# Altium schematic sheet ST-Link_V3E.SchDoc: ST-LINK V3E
size A3; Project: STLink V3 Embedded Prototype; BOM Version: A-01; Date: Not used; ApprovedBy: Not used; CheckedBy: Not used; Author: Not used; CompanyName: STMicroelectronics; DrawnBy: Not used; Engineer: Not used; Organization: Not used; Address1: Not used; Address2: Not used; Address3: Not used; Address4: Not used; DocumentNumber: 17; Revision: Not used; SheetNumber: 17; SheetTotal: 17
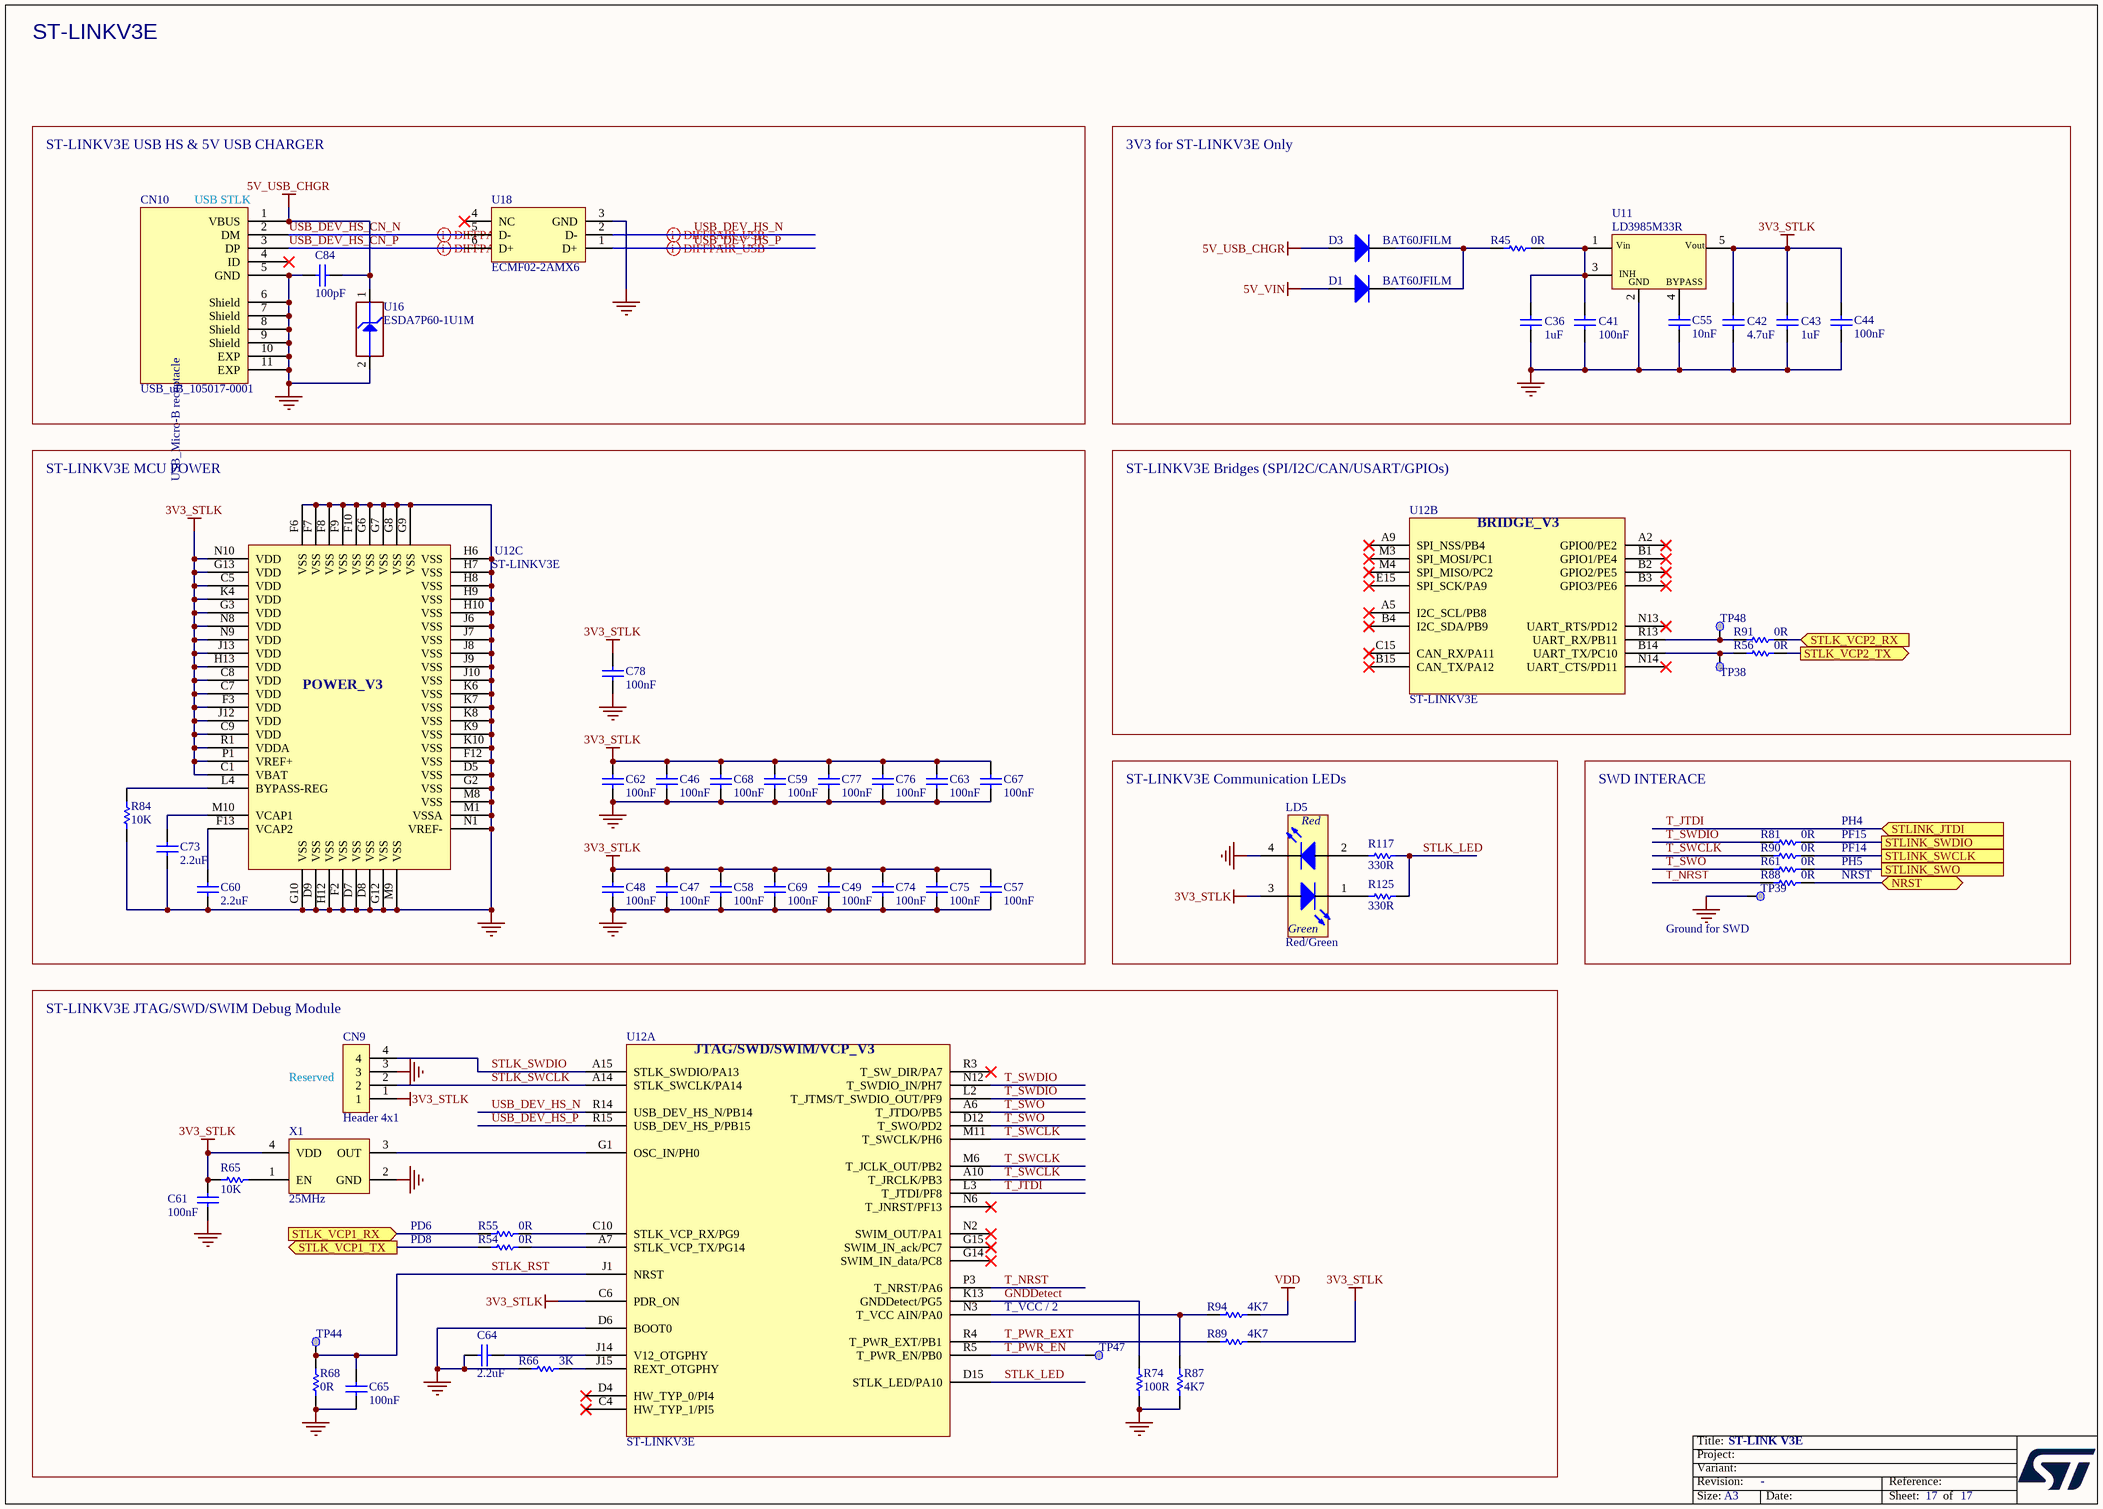
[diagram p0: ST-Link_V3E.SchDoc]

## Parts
C36  value 1uF  [C0402]  (hidden comment: Capacitor)
C41  value 100nF  [C0402]  (hidden comment: Capacitor)
C42  value 4.7uF  [C0402]  (hidden comment: Capacitor)
C43  value 1uF  [C0402]  (hidden comment: Capacitor)
C44  value 100nF  [C0402]  (hidden comment: Capacitor)
C46  value 100nF  [C0402]  (hidden comment: Capacitor)
C47  value 100nF  [C0402]  (hidden comment: Capacitor)
C48  value 100nF  [C0402]  (hidden comment: Capacitor)
C49  value 100nF  [C0402]  (hidden comment: Capacitor)
C55  value 10nF  [C0402]  (hidden comment: Capacitor)
C57  value 100nF  [C0402]  (hidden comment: Capacitor)
C58  value 100nF  [C0402]  (hidden comment: Capacitor)
C59  value 100nF  [C0402]  (hidden comment: Capacitor)
C60  value 2.2uF  [C0201_H0P5]  (hidden comment: Capacitor)
C61  value 100nF  [C0402]  (hidden comment: Capacitor)
C62  value 100nF  [C0402]  (hidden comment: Capacitor)
C63  value 100nF  [C0402]  (hidden comment: Capacitor)
C64  value 2.2uF  [C0201_H0P5]  (hidden comment: Capacitor)
C65  value 100nF  [C0402]  (hidden comment: Capacitor)
C67  value 100nF  [C0402]  (hidden comment: Capacitor)
C68  value 100nF  [C0402]  (hidden comment: Capacitor)
C69  value 100nF  [C0402]  (hidden comment: Capacitor)
C73  value 2.2uF  [C0201_H0P5]  (hidden comment: Capacitor)
C74  value 100nF  [C0402]  (hidden comment: Capacitor)
C75  value 100nF  [C0402]  (hidden comment: Capacitor)
C76  value 100nF  [C0402]  (hidden comment: Capacitor)
C77  value 100nF  [C0402]  (hidden comment: Capacitor)
C78  value 100nF  [C0402]  (hidden comment: Capacitor)
C84  value 100pF  [C0402]  (hidden comment: Capacitor)
CN9  Header 4x1  [CON_SAMTEC_TSW-104-07-G-S]
CN10  value USB_uB_105017-0001  [CON_USBMICROB_MOLEX_105017-0001_H2P90]  (hidden comment: USB_uB_105017.0001)
D1  BAT60JFILM  [DIO_SOD323]
D3  BAT60JFILM  [DIO_SOD323]
LD5  value Red/Green  [LED_BI-GR_CMD67-22]  (hidden comment: LD_BICOLOR_VCC)
R45  value 0R  [R0402]  (hidden comment: Resistor)
R54  value 0R  [R0402]  (hidden comment: Resistor)
R55  value 0R  [R0402]  (hidden comment: Resistor)
R56  value 0R  [R0402]  (hidden comment: Resistor)
R61  value 0R  [R0402]  (hidden comment: Resistor)
R65  value 10K  [R0402]  (hidden comment: Resistor)
R66  value 3K  [R0402]  (hidden comment: Resistor)
R68  value 0R  [R0402]  (hidden comment: Resistor)
R74  value 100R  [R0402]  (hidden comment: Resistor)
R81  value 0R  [R0402]  (hidden comment: Resistor)
R84  value 10K  [R0402]  (hidden comment: Resistor)
R87  value 4K7  [R0402]  (hidden comment: Resistor)
R88  value 0R  [R0402]  (hidden comment: Resistor)
R89  value 4K7  [R0402]  (hidden comment: Resistor)
R90  value 0R  [R0402]  (hidden comment: Resistor)
R91  value 0R  [R0402]  (hidden comment: Resistor)
R94  value 4K7  [R0402]  (hidden comment: Resistor)
R117  value 330R  [R0402]  (hidden comment: Resistor)
R125  value 330R  [R0402]  (hidden comment: Resistor)
TP38  Test Point  [TP_SMD_1MM]  (value not drawn)  (no BOM)
TP39  Test Point  [TP_SMD_1MM]  (value not drawn)  (no BOM)
TP44  Test Point  [TP_SMD_1MM]  (value not drawn)  (no BOM)
TP47  Test Point  [TP_SMD_1MM]  (value not drawn)  (no BOM)
TP48  Test Point  [TP_SMD_1MM]  (value not drawn)  (no BOM)
U11  LD3985M33R  [REG_SOT23-5L]
U12  ST-LINKV3E  [ICC_UFBGA201_176+25_10X10_P065]  (parts A,B,C of 3)
U16  value ESDA7P60-1U1M  [ESD_QFN2_1P6X1_P125]  (hidden comment: ESD-TRANSIL)
U18  ECMF02-2AMX6  [ESD_QFN-6L_1P7X1P5_P050]
X1  value 25MHz  [OSC_NDK_NZ2520SB_4P]  (hidden comment: OSCILLATOR_4_PINS)

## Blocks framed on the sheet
ST-LINKV3E USB HS & 5V USB CHARGER: C84 CN10 U16 U18
3V3 for ST-LINKV3E Only: C36 C41-C44 C55 D1 D3 R45 U11
ST-LINKV3E MCU POWER: C46-C49 C57-C60 C62 C63 C67-C69 C73-C78 R84 U12
ST-LINKV3E Bridges (SPI/I2C/CAN/USART/GPIOs): R56 R91 TP38 TP48 U12
ST-LINKV3E Communication LEDs: LD5 R117 R125
SWD INTERACE: R61 R81 R88 R90 TP39
ST-LINKV3E JTAG/SWD/SWIM Debug Module: C61 C64 C65 CN9 R54 R55 R65 R66 R68 R74 R87 R89 R94 TP44 TP47 U12 X1

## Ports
NRST (bidir), STLINK_JTDI (in), STLINK_SWCLK, STLINK_SWDIO, STLINK_SWO, STLK_VCP1_RX (in), STLK_VCP1_TX (out), STLK_VCP2_RX (in), STLK_VCP2_TX (out)

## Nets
3V3_STLK: C42.2 C43.2 C44.2 C46.2 C47.2 C48.2 C49.2 C57.2 C58.2 C59.2 C61.2 C62.2 C63.2 C67.2 C68.2 C69.2 C74.2 C75.2 C76.2 C77.2 C78.2 CN9.1 LD5.3(YellowGreen_anode) R65.1 R89.1 U11.5(Vout) U12.C1(VBAT) U12.C5(VDD) U12.C6(PDR_ON) U12.C7(VDD) U12.C8(VDD) U12.C9(VDD) U12.F3(VDD) U12.G3(VDD) U12.G13(VDD) U12.H13(VDD) U12.J12(VDD) U12.J13(VDD) U12.K4(VDD) U12.N8(VDD) U12.N9(VDD) U12.N10(VDD) U12.P1(VREF+) U12.R1(VDDA) X1.4(VDD)
5V_USB_CHGR: C84.2 CN10.1(VBUS) D3.1(A) U16.1(IO1)
5V_VIN: D1.1(A)
GND: C36.2 C41.1 C42.1 C43.1 C44.1 C46.1 C47.1 C48.1 C49.1 C55.1 C57.1 C58.1 C59.1 C60.1 C61.1 C62.1 C63.1 C64.1 C65.1 C67.1 C68.1 C69.1 C73.1 C74.1 C75.1 C76.1 C77.1 C78.1 C84.1 CN9.3 CN10.5(GND) CN10.6(Shield) CN10.7(Shield) CN10.8(Shield) CN10.9(Shield) CN10.10(EXP) CN10.11(EXP) LD5.4(RED_cathode) R66.1 R68.2 R74.1 R84.1 R87.1 TP39.1 U11.2(GND) U12.D5(VSS) U12.D6(BOOT0) U12.D7(VSS) U12.D8(VSS) U12.D9(VSS) U12.F2(VSS) U12.F6(VSS) U12.F7(VSS) U12.F8(VSS) U12.F9(VSS) U12.F10(VSS) U12.F12(VSS) U12.G2(VSS) U12.G6(VSS) U12.G7(VSS) U12.G8(VSS) U12.G9(VSS) U12.G10(VSS) U12.G12(VSS) U12.H6(VSS) U12.H7(VSS) U12.H8(VSS) U12.H9(VSS) U12.H10(VSS) U12.H12(VSS) U12.J6(VSS) U12.J7(VSS) U12.J8(VSS) U12.J9(VSS) U12.J10(VSS) U12.K6(VSS) U12.K7(VSS) U12.K8(VSS) U12.K9(VSS) U12.K10(VSS) U12.M1(VSSA) U12.M8(VSS) U12.M9(VSS) U12.N1(VREF-) U16.2(GND) U18.3(GND) X1.2(GND)
VDD: R94.2
GNDDetect: R74.2 U12.K13(GNDDetect/PG5)
NRST: R88.2 ; port NRST
STLINK_SWCLK: R90.2 ; port STLINK_SWCLK
STLINK_SWDIO: R81.2 ; port STLINK_SWDIO
STLINK_SWO: R61.2 ; port STLINK_SWO
STLK_LED: R117.2 R125.2 U12.D15(STLK_LED/PA10)
STLK_RST: C65.2 R68.1 TP44.1 U12.J1(NRST)
STLK_SWCLK: CN9.2 U12.A14(STLK_SWCLK/PA14)
STLK_SWDIO: CN9.4 U12.A15(STLK_SWDIO/PA13)
STLK_VCP1_RX: R55.2 ; port STLK_VCP1_RX
STLK_VCP1_TX: R54.2 ; port STLK_VCP1_TX
STLK_VCP2_RX: R91.1 ; port STLK_VCP2_RX
STLK_VCP2_TX: R56.1 ; port STLK_VCP2_TX
T_JTDI: U12.L3(T_JTDI/PF8) ; port STLINK_JTDI
T_NRST: R88.1 U12.P3(T_NRST/PA6)
T_PWR_EN: TP47.1 U12.R5(T_PWR_EN/PB0)
T_PWR_EXT: R89.2 U12.R4(T_PWR_EXT/PB1)
T_SWCLK: R90.1 U12.A10(T_JRCLK/PB3) U12.M6(T_JCLK_OUT/PB2) U12.M11(T_SWCLK/PH6)
T_SWDIO: R81.1 U12.L2(T_JTMS/T_SWDIO_OUT/PF9) U12.N12(T_SWDIO_IN/PH7)
T_SWO: R61.1 U12.A6(T_JTDO/PB5) U12.D12(T_SWO/PD2)
USB_DEV_HS_CN_N: CN10.2(DM) U18.5(D-)
USB_DEV_HS_CN_P: CN10.3(DP) U18.6(D+)
USB_DEV_HS_N: U12.R14(USB_DEV_HS_N/PB14) U18.2(D-)
USB_DEV_HS_P: U12.R15(USB_DEV_HS_P/PB15) U18.1(D+)
NetC36_1: C36.1 C41.2 R45.2 U11.1(Vin) U11.3(CE)
NetC55_2: C55.2 U11.4(BYPASS)
NetC60_2: C60.2 U12.F13(VCAP2)
NetC64_2: C64.2 U12.J14(V12_OTGPHY)
NetC73_2: C73.2 U12.M10(VCAP1)
NetD1_2: D1.2(K) D3.2(K) R45.1
NetLD5_1: LD5.1(YellowGreen_cathode) R125.1
NetLD5_2: LD5.2(Red_anode) R117.1
NetR54_1: R54.1 U12.A7(STLK_VCP_TX/PG14)
NetR55_1: R55.1 U12.C10(STLK_VCP_RX/PG9)
NetR56_2: R56.2 TP38.1 U12.B14(UART_TX/PC10)
NetR65_2: R65.2 X1.1(EN)
NetR66_2: R66.2 U12.J15(REXT_OTGPHY)
NetR84_2: R84.2 U12.L4(BYPASS-REG)
NetR87_2: R87.2 R94.1 U12.N3(T_VCC_AIN/PA0)
NetR91_2: R91.2 TP48.1 U12.R13(UART_RX/PB11)
NetU12_G1: U12.G1(OSC_IN/PH0) X1.3(OUT)

Not connected (* = marked no-connect by the designer): CN10 4(ID)*; U12 A2(GPIO0/PE2)* A5(I2C_SCL/PB8)* A9(SPI_NSS/PB4)* B1(GPIO1/PE4)* B2(GPIO2/PE5)* B3(GPIO3/PE6)* B4(I2C_SDA/PB9)* B15(CAN_TX/PA12)* C4(HW_TYP_1/PI5)* C15(CAN_RX/PA11)* D4(HW_TYP_0/PI4)* E15(SPI_SCK/PA9)* G14(SWIM_IN_data/PC8)* G15(SWIM_IN_ack/PC7)* M3(SPI_MOSI/PC1)* M4(SPI_MISO/PC2)* N2(SWIM_OUT/PA1)* N6(T_JNRST/PF13)* N13(UART_RTS/PD12)* N14(UART_CTS/PD11)* R3(T_SW_DIR/PA7)*; U18 4(NC)*

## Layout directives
differential pair; rule Impedance Constraint [Min = 85.00    Max = 95.00    ]: USB_DEV_HS_CN_N, USB_DEV_HS_CN_P, USB_DEV_HS_N, USB_DEV_HS_P

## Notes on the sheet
- ST-LINKV3E
- (near CN10) USB STLK
- PF14
- PF15
- PH4
- NRST
- PH5
- Ground for SWD
- (near CN9) Reserved
- PD8
- PD6
- T_VCC / 2

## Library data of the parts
C36 C43 = MCD-00095: Capacitor, MLCC, 1uF, 25V, X5R, +/-10%, 0402, T=0.5mm; Manufacturer_Part_Number: GRM155R61E105KA12; Manufacturer: MURATA; Part_Preference: Recommended; Partial_Alternate_Internal_Part_Number: MCD-04188; Order_Code_RS: 2218855; Component_Country_Of_Origin: Japan°°; ShowFields: YES; ID: 2772
C41 C44 C46-C49 C57-C59 C61-C63 C67-C69 C74-C78 = MCD-00006: Capacitor, MLCC, 100nF, 16V, X7R, +/-10%, 0402, T=0.5mm; Manufacturer_Part_Number: CC0402KRX7R7BB104; Manufacturer: YAGEO; Part_Preference: Recommended; Partial_Alternate_Internal_Part_Number: MCD-03299; Order_Code_RS: 9402047; Component_Country_Of_Origin: China; ShowFields: YES; ID: 2474
C42 = MCD-01356: Capacitor, MLCC, 4.7uF, 6V3, X5R, +/-20%, 0402, T=0.5mm; Manufacturer_Part_Number: GRM155R60J475ME47; Manufacturer: MURATA; Part_Preference: Recommended; Partial_Alternate_Internal_Part_Number: MCD-04455; Order_Code_RS: 814-5230; Component_Country_Of_Origin: Japan°°; ShowFields: YES; ID: 3456
C55 = MCD-02198: Capacitor, MLCC, 10nF, 50V, X7R, +/-10%, 0402, T=0.5mm; Manufacturer_Part_Number: CC0402KRX7R9BB103; Manufacturer: YAGEO; Part_Preference: Recommended; Order_Code_RS: 6169644; Component_Country_Of_Origin: China; ShowFields: YES; ID: 4298
C60 C64 C73 = MCD-02235: Capacitor, MLCC, 2.2uF, 10V, X5R,+/-10%, 0201, T=0.5mm; Manufacturer_Part_Number: GRM033R61A225KE47; Manufacturer: MURATA; Part_Preference: Recommended; Order_Code_RS: NA; Component_Country_Of_Origin: Japan°°; ShowFields: YES; ID: 4335
C65 = MCD-00006: Capacitor, MLCC, 100nF, 16V, X7R, +/-10%, 0402, T=0.5mm; Part_Preference: Recommended; Manufacturer: YAGEO; Manufacturer_Part_Number: CC0402KRX7R7BB104; Partial_Alternate_Internal_Part_Number: MCD-03299; Order_Code_RS: 9402047; Component_Country_Of_Origin: China; ShowFields: YES; ID: 2474
C84 = MCD-00205: Capacitor, MLCC, 100pF, 50V, NPO, +/-5%, 0402, T=0.5mm; Manufacturer_Part_Number: CC0402JRNPO9BN101; Manufacturer: YAGEO; Part_Preference: Recommended; Component_Country_Of_Origin: China; ShowFields: YES; ID: 2658
CN9 = MCD-00029: Header, 4x1, 2.54mm, VR, TH, T=5.84mm/2.54mm; Part_Type: Connector; Manufacturer_Part_Number: TSW-104-07-G-S; Manufacturer: SAMTEC; Part_Preference: Recommended; Partial_Alternate_Internal_Part_Number: MCD-04227; Order_Code_RS: 161-2460; Component_Country_Of_Origin: China, Costa Rica, Malaysia, USA, Vietnam; ShowFields: YES; ID: 2487
CN10 = MCD-00028: MicroUSB_TypeB, 5pins, 0.65mm, RA, SMD, T=2.9mm; Manufacturer_Part_Number: 1050170001; Manufacturer: MOLEX; Part_Type: Connector; Part_Preference: Recommended; Partial_Alternate_Internal_Part_Number: MCD-04277; Order_Code_RS: 2293836; Component_Country_Of_Origin: Unknown; ShowFields: YES; ID: 2489
D1 D3 = MCD-00034: Manufacturer: STMICROELECTRONICS; Part_Type: Diode; BMS_Part_Number: 9151097; Part_Preference: Recommended; Manufacturer_HQ_COO: EU; Component_Country_Of_Origin: China; ShowFields: YES; ID: 2483; Order_Code_RS: 714-6879
LD5 = MCD-02629: LED Bicolor, Green, Red, 4-PLCC; Part_Type: Display; Manufacturer_Part_Number: CMD6722VRVGCTR8; Manufacturer: VISUAL COMMUNICATIONS COMPANY; Part_Preference: Forbidden; ShowFields: YES; ID: 4735; Component_Country_Of_Origin: USA
R45 R61 R81 R88 R90 = MCD-00052: Resistor, 0R, 0402, +/-5%, 1/16W; Part_Preference: Recommended; Manufacturer: YAGEO; Manufacturer_Part_Number: RC0402JR-070RL; Order_Code_RS: 9232516RL; Component_Country_Of_Origin: China; ShowFields: YES; ID: 2540
R54-R56 R68 R91 = MCD-00052: Resistor, 0R, 0402, +/-5%, 1/16W; Manufacturer_Part_Number: RC0402JR-070RL; Manufacturer: YAGEO; Part_Preference: Recommended; Order_Code_RS: 9232516RL; Component_Country_Of_Origin: China; ShowFields: YES; ID: 2540
R65 R84 = MCD-00053: Resistor, 10K, 0402, +/-1%, 1/16W; Manufacturer_Part_Number: RC0402FR-0710KL; Manufacturer: YAGEO; BMS_Part_Number: 9131590; Part_Preference: Recommended; Order_Code_RS: 9239359; Component_Country_Of_Origin: China; ShowFields: YES; ID: 2539
R66 = MCD-00185: Resistor, 3K, 0402, +/-1%, 1/16W; Manufacturer_Part_Number: RC0402FR-073KL; Manufacturer: YAGEO; Part_Preference: Recommended; Component_Country_Of_Origin: China; ShowFields: YES; ID: 2682
R74 = MCD-00067: Resistor, 100R, 0402, +/- 1%, 1/16W; Manufacturer_Part_Number: RC0402FR-07100RL; Manufacturer: YAGEO; Part_Preference: Recommended; Order_Code_RS: 9239111; Component_Country_Of_Origin: China; ShowFields: YES; ID: 2527
R87 R89 R94 = MCD-00065: Resistor, 4K7, 0402, +/-1%, 1/16W; Manufacturer_Part_Number: RC0402FR-074K7L; Manufacturer: YAGEO; Part_Preference: Recommended; Partial_Alternate_Internal_Part_Number: MCD-03300; Order_Code_RS: 9239316; Component_Country_Of_Origin: China; ShowFields: YES; ID: 2526
R117 R125 = MCD-00062: Resistor, 330R, 0402, +/-1%, 1/16W; Manufacturer_Part_Number: RC0402FR-07330RL; Manufacturer: YAGEO; Part_Preference: Recommended; Order_Code_RS: 9239170; Component_Country_Of_Origin: China; ShowFields: YES; ID: 2529
TP38 TP39 TP44 TP47 TP48 = MCD-00074: Test Point 1mm; Part_Type: Misc; Part_Preference: Recommended; ShowFields: YES; ID: 2518; Component_Country_Of_Origin: Unknown
U11 = MCD-00086: Ultra low drop-low noise BiCMOS voltage, regulators low ESR capacitors compatible; BMS_Part_Number: 9176161; Part_Preference: Recommended; Part_Type: IC; Manufacturer: STMICROELECTRONICS; Manufacturer_HQ_COO: EU; Component_Country_Of_Origin: China; ShowFields: YES; ID: 2506; Order_Code_RS: 168-6500
U12 = MCD-01523: MCU, Arm Cortex-M7 32-bit MCU, 512KB Flash, 276KB RAM, With Crypto; Part_Type: IC; Manufacturer: STMICROELECTRONICS; Part_Preference: Not recommended; Manufacturer_HQ_COO: EU; BMS_Part_Number: 9175300; Value: STM32F723IEK6; Component_Country_Of_Origin: Philippines; ShowFields: YES; ID: 3623; Order_Code_RS: 135-8241
U16 = MCD-00251: High power transient voltage suppressor, 7V breakdown; Part_Type: Diode; Manufacturer: STMICROELECTRONICS; BMS_Part_Number: 9179042; Part_Preference: Recommended; Manufacturer_HQ_COO: EU; Component_Country_Of_Origin: China; ShowFields: YES; ID: 2618; Order_Code_RS: 110-6381
U18 = MCD-00649: Common mode filter with ESD protection for USB 2.0 interface; Part_Type: Diode; Manufacturer: STMICROELECTRONICS; BMS_Part_Number: 9151138; Part_Preference: Recommended; Manufacturer_HQ_COO: EU; Component_Country_Of_Origin: China; ShowFields: YES; ID: 3094; Order_Code_RS: 880-5276
X1 = MCD-00597: Oscillator, SPXO, 25Mhz, +/-50ppm, 3V3, square wave, 2.5x2mm; Manufacturer_Part_Number: NZ2520SH-25MHZ-END4869C; Manufacturer: NDK; Part_Type: Crystal_Osc; BMS_Part_Number: 9157050; Part_Preference: Recommended; Component_Country_Of_Origin: Japan; ShowFields: YES; ID: 3148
